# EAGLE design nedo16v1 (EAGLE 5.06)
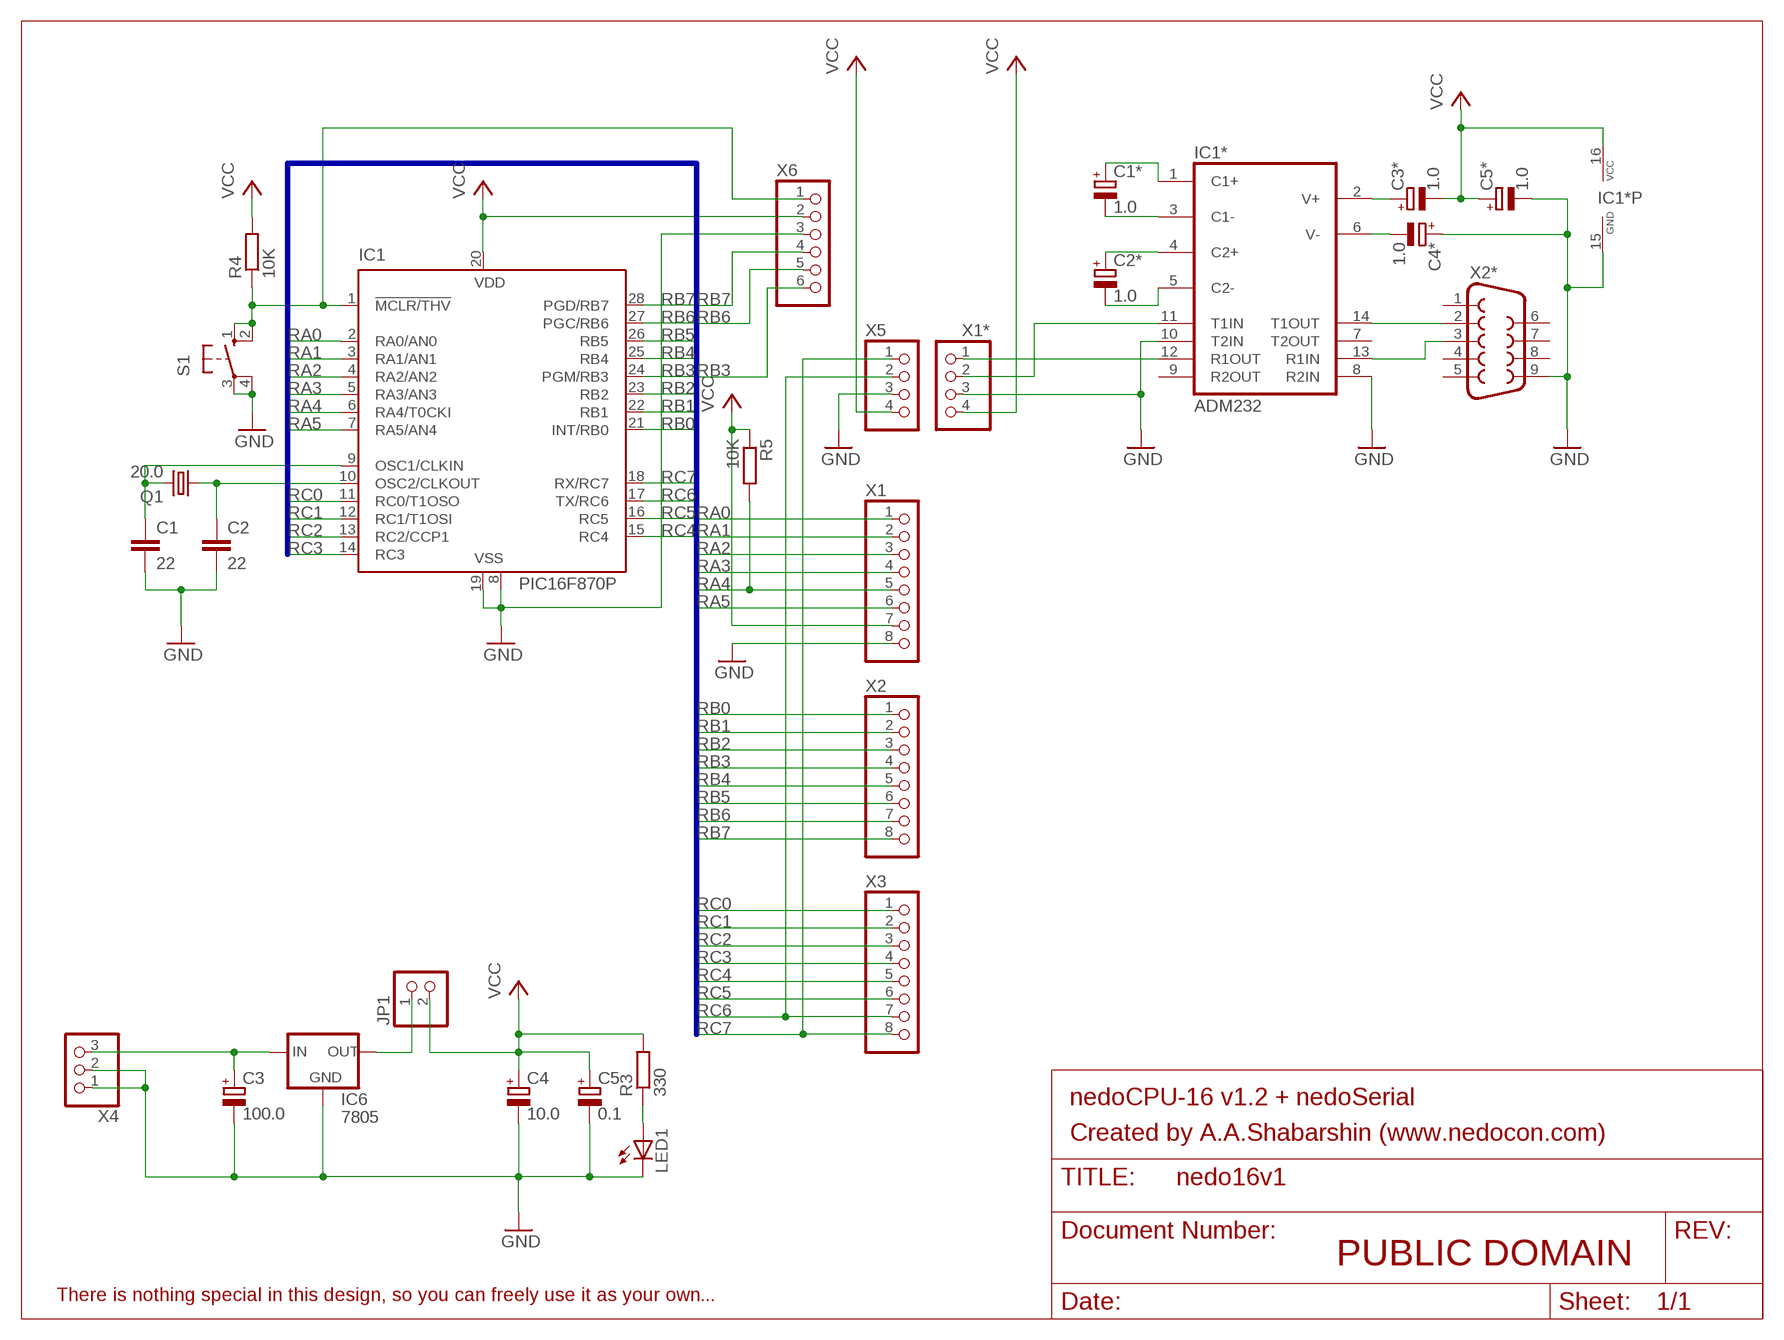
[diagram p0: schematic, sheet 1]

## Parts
C1  22  C-EU025-024X044  [C025-024X044]
C1*  1.0  CPOL-EUE2,5-6E  [E2,5-6E]
C2  22  C-EU025-024X044  [C025-024X044]
C2*  1.0  CPOL-EUE2,5-6E  [E2,5-6E]
C3  100.0  CPOL-EUE5-6  [E5-6]
C3*  1.0  CPOL-EUE2,5-6E  [E2,5-6E]
C4  10.0  CPOL-EUE2.5-6  [E2,5-6]
C4*  1.0  CPOL-EUE2,5-6E  [E2,5-6E]
C5  0.1  CPOL-EUE5-5  [E5-5]
C5*  1.0  CPOL-EUE2,5-6E  [E2,5-6E]
IC1  PIC16F870P  [DIL28-3]
IC1*  ADM232  MAX232  [DIL16]
IC6  7805  78XXS  [78XXS]
JP1  PINHD-1X2  [1X02]
LED1  LED5MM  [LED5MM]
Q1  20.0  CRYSTALHC49U-V  [HC49U-V]
R3  330  R-EU_0204/7  [0204/7]
R4  10K  R-EU_0204/7  [0204/7]
R5  10K  R-EU_0207/7  [0207/7]
S1  10-XX  [B3F-10XX]
X1  PINHD-1X8  [1X08]
X1*  PINHD-1X4  [1X04]
X2  PINHD-1X8  [1X08]
X2*  F09HP  [F09HP]
X3  PINHD-1X8  [1X08]
X4  PINHD-1X3  [1X03]
X5  PINHD-1X4  [1X04]
X6  PINHD-1X6  [1X06]

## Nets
GND: C1.2 C2.2 C3.- C4*.+ C4.- C5*.- C5.- IC1*.8(R2IN) IC1*.10(T2IN) IC1*.15(GND) IC1.8(VSS) IC1.19(VSS) IC6.GND LED1.K(C) S1.3(P) S1.4(P1) X1*.3 X1.8 X2*.9 X4.1 X4.2 X5.3 X6.3
N$1: IC1*.14(T1OUT) X2*.2
N$2: IC6.OUT JP1.1
N$3: IC1.1(!MCLR/THV) R4.1 S1.1(S) S1.2(S1) X6.1
N$7: LED1.A R3.1
N$10: C2.1 IC1.10(OSC2/CLKOUT) Q1.1
N$12: IC1*.13(R1IN) X2*.3
N$13: C4*.- IC1*.6(V-)
N$14: C3.+ IC6.IN X4.3
N$15: C3*.+ IC1*.2(V+)
N$16: C1.1 IC1.9(OSC1/CLKIN) Q1.2
N$17: C1*.- IC1*.3(C1-)
N$18: C2*.+ IC1*.4(C2+)
N$19: C2*.- IC1*.5(C2-)
N$20: C1*.+ IC1*.1(C1+)
RA0: IC1.2(RA0/AN0) X1.1
RA1: IC1.3(RA1/AN1) X1.2
RA2: IC1.4(RA2/AN2) X1.3
RA3: IC1.5(RA3/AN3) X1.4
RA4: IC1.6(RA4/T0CKI) R5.2 X1.5
RA5: IC1.7(RA5/AN4) X1.6
RB0: IC1.21(INT/RB0) X2.1
RB1: IC1.22(RB1) X2.2
RB2: IC1.23(RB2) X2.3
RB3: IC1.24(PGM/RB3) X2.4 X6.6
RB4: IC1.25(RB4) X2.5
RB5: IC1.26(RB5) X2.6
RB6: IC1.27(PGC/RB6) X2.7 X6.5
RB7: IC1.28(PGD/RB7) X2.8 X6.4
RC0: IC1.11(RC0/T1OSO) X3.1
RC1: IC1.12(RC1/T1OSI) X3.2
RC2: IC1.13(RC2/CCP1) X3.3
RC3: IC1.14(RC3) X3.4
RC4: IC1.15(RC4) X3.5
RC5: IC1.16(RC5) X3.6
RC6: IC1*.11(T1IN) IC1.17(TX/RC6) X1*.2 X3.7 X5.2
RC7: IC1*.12(R1OUT) IC1.18(RX/RC7) X1*.1 X3.8 X5.1
VCC: C3*.- C4.+ C5*.+ C5.+ IC1*.16(VCC) IC1.20(VDD) JP1.2 R3.2 R4.2 R5.1 X1*.4 X1.7 X5.4 X6.2
Unconnected: IC1*.7(T2OUT) IC1*.9(R2OUT) X2*.1 X2*.4 X2*.5 X2*.6 X2*.7 X2*.8

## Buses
RA[0..5],RB[0..7],RC[0..7]

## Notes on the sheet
- nedoCPU-16 v1.2 + nedoSerial
- Created by A.A.Shabarshin (www.nedocon.com)
- PUBLIC DOMAIN
- There is nothing special in this design, so you can freely use it as your own...

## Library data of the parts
C1 C2 = rcl:C-EU: CAPACITOR, European symbol
C1* C2* C3 C3* C4 C4* C5 C5* = rcl:CPOL-EU: POLARIZED CAPACITOR, European symbol
IC1 = microchip:PIC16*870: MICROCONTROLLER flash type
IC1* = maxim:MAX232: RS232 TRANSEIVER
IC6 = v-reg:78XXS: VOLTAGE REGULATOR
JP1 = pinhead:PINHD-1X2: PIN HEADER
LED1 = led:LED: LED
Q1 = crystal:CRYSTAL: CRYSTAL
R3-R5 = rcl:R-EU_: RESISTOR, European symbol
S1 = switch-omron:10-XX: OMRON SWITCH
X1-X3 = pinhead:PINHD-1X8: PIN HEADER
X1* X5 = pinhead:PINHD-1X4: PIN HEADER
X2* = con-subd:F09: SUB-D
X4 = pinhead:PINHD-1X3: PIN HEADER
X6 = pinhead:PINHD-1X6: PIN HEADER

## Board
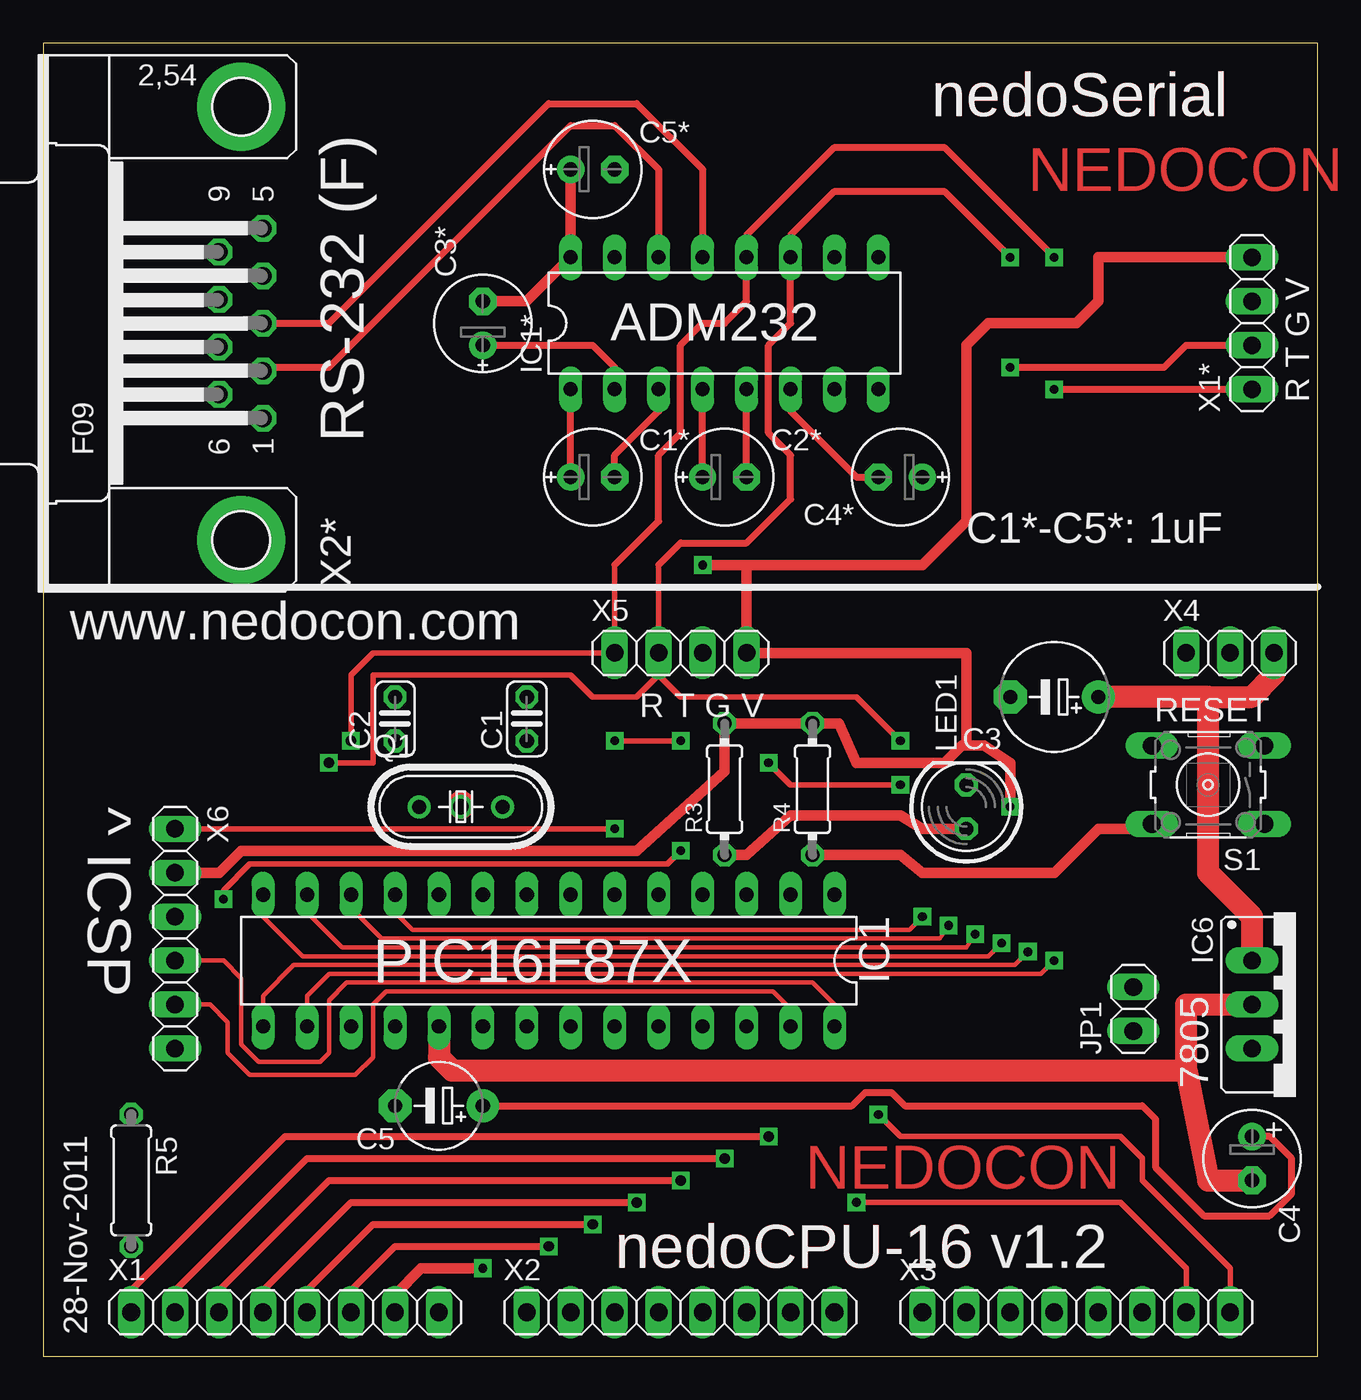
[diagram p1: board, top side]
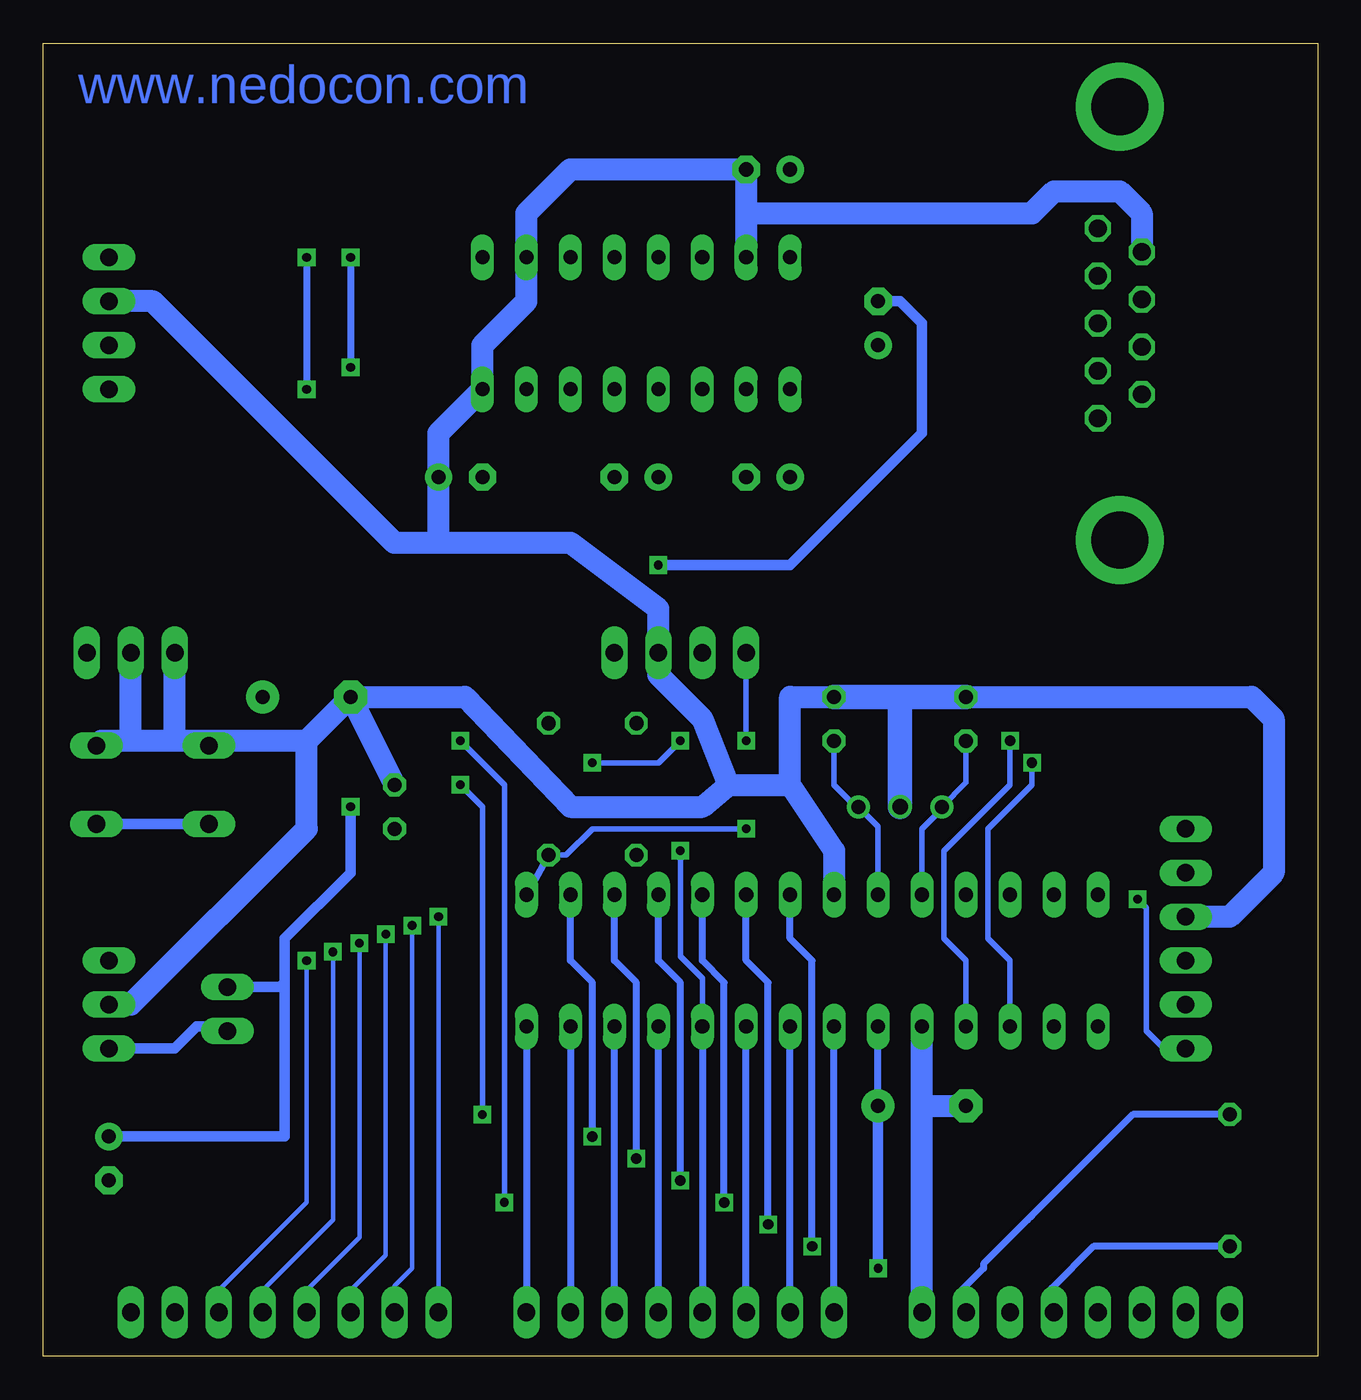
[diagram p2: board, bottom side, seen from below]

Size 73.64 x 75.87 mm. Coordinates in mm from the lower left corner, seen from the top.
Outline: 0,0 73.64,0 73.64,75.87 0,75.87 0,0
Copper layers (1*16): Top 0.035mm / dielectric 1.5mm / Bottom 0.035mm
Design rules "default *": minimum track width 10mil, minimum drill 16mil, track to track 10mil, track to pad 10mil, pad to pad 10mil, via to via 10mil, smd to smd 10mil, copper to edge 40mil, drill to drill 8mil, minimum pad ring 10mil, minimum via ring 8mil, stop-mask expansion 4mil, vias tented up to drill 0mil, thermal gap 10mil

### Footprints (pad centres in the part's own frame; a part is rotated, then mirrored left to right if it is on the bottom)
C025-024X044 = drill 0.813 octagon: 1 -1.27,0; 2 1.27,0
E2,5-6E = drill 0.813 pad 1.575 round: + -1.27,0 | drill 0.813 pad 1.575 octagon: - 1.27,0
E5-6 = drill 0.813 pad 1.905 round: + -2.54,0 | drill 0.813 pad 1.905 octagon: - 2.54,0
E2,5-6 = drill 0.813 pad 1.6 round: + -1.27,0 | drill 0.813 pad 1.6 octagon: - 1.27,0
E5-5 = drill 0.813 pad 1.905 round: + -2.54,0 | drill 0.813 pad 1.905 octagon: - 2.54,0
DIL28-3 = drill 0.813 long: 1 -16.51,-3.81; 2 -13.97,-3.81; 3 -11.43,-3.81; 4 -8.89,-3.81; 5 -6.35,-3.81; 6 -3.81,-3.81; 7 -1.27,-3.81; 8 1.27,-3.81; 9 3.81,-3.81; 10 6.35,-3.81; 11 8.89,-3.81; 12 11.43,-3.81; 13 13.97,-3.81; 14 16.51,-3.81; 15 16.51,3.81; 16 13.97,3.81; 17 11.43,3.81; 18 8.89,3.81; 19 6.35,3.81; 20 3.81,3.81; 21 1.27,3.81; 22 -1.27,3.81; 23 -3.81,3.81; 24 -6.35,3.81; 25 -8.89,3.81; 26 -11.43,3.81; 27 -13.97,3.81; 28 -16.51,3.81
DIL16 = drill 0.813 long: 1 -8.89,-3.81; 2 -6.35,-3.81; 3 -3.81,-3.81; 4 -1.27,-3.81; 5 1.27,-3.81; 6 3.81,-3.81; 7 6.35,-3.81; 8 8.89,-3.81; 9 8.89,3.81; 10 6.35,3.81; 11 3.81,3.81; 12 1.27,3.81; 13 -1.27,3.81; 14 -3.81,3.81; 15 -6.35,3.81; 16 -8.89,3.81
78XXS = drill 1.016 long: GND 0,-2.54; IN -2.54,-2.54; OUT 2.54,-2.54
1X02 = drill 1.016 long: 1 -1.27,0; 2 1.27,0
LED5MM = drill 0.813 octagon: A -1.27,0; K 1.27,0
HC49U-V = drill 0.813 round: 1 -2.413,0; 2 2.413,0
0204/7 = drill 0.813 octagon: 1 -3.81,0; 2 3.81,0
0207/7 = drill 0.813 octagon: 1 -3.81,0; 2 3.81,0
B3F-10XX = drill 1.016 long: 1 -3.251,2.261; 2 3.251,2.261; 3 -3.251,-2.261; 4 3.251,-2.261
1X08 = drill 1.016 long: 1 -8.89,0; 2 -6.35,0; 3 -3.81,0; 4 -1.27,0; 5 1.27,0; 6 3.81,0; 7 6.35,0; 8 8.89,0
1X04 = drill 1.016 long: 1 -3.81,0; 2 -1.27,0; 3 1.27,0; 4 3.81,0
F09HP = drill 1.016 octagon: 1 -5.486,-1.27; 2 -2.743,-1.27; 3 0,-1.27; 4 2.743,-1.27; 5 5.486,-1.27; 6 -4.115,1.27; 7 -1.372,1.27; 8 1.372,1.27; 9 4.115,1.27 | drill 3.302 pad 5.08 round: G1 -12.522,0; G2 12.522,0
1X03 = drill 1.016 long: 1 -2.54,0; 2 0,0; 3 2.54,0
1X06 = drill 1.016 long: 1 -6.35,0; 2 -3.81,0; 3 -1.27,0; 4 1.27,0; 5 3.81,0; 6 6.35,0

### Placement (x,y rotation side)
C1  27.94,36.83 90 top
C1*  31.75,50.8 0 top
C2  20.32,36.83 90 top
C2*  39.37,50.8 0 top
C3  58.42,38.1 180 top
C3*  25.4,59.69 90 top
C4  69.85,11.43 270 top
C4*  49.53,50.8 180 top
C5  22.86,14.48 180 top
C5*  31.75,68.58 0 top
IC1  29.21,22.86 180 top
IC1*  39.37,59.69 0 top
IC6  72.39,20.32 270 top
JP1  62.99,20.07 90 top
LED1  53.34,31.75 90 top
Q1  24.13,31.75 0 top
R3  39.37,32.77 90 top
R4  44.45,32.77 90 top
R5  5.08,10.16 270 top
S1  67.31,33.02 180 top
X1  13.97,2.54 0 top
X1*  69.85,59.69 90 top
X2  36.83,2.54 0 top
X2*  11.43,59.69 90 top
X3  59.69,2.54 0 top
X4  68.58,40.64 0 top
X5  36.83,40.64 0 top
X6  7.62,24.13 270 top

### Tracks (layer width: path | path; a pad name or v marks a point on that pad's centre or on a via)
GND  (via drill 0.9)
  Top 1.27: IC1.19 22.86,17.27 23.62,16.51 66.04,16.51 | 66.04,16.51 66.04,20.32 IC6.GND | 66.04,16.51 67.31,10.16 C4.-
  Top 1.422: v24.13,31.75 24.13,32
  Bottom 1.27: 22.86,14.48 IC1.19 | X1.8 22.86,14.48 | 22.86,14.48 C5.- | 58.42,35.56 63.78,35.56 | 63.78,35.56 S1.4 | 63.78,35.56 66.04,35.56 | 66.04,35.56 68.58,35.56 | 68.58,35.56 70.28,35.56 S1.3 | 68.58,35.56 X4.2 | 66.04,35.56 X4.1 | C3.- LED1.K | 58.42,35.56 58.42,30.48 68.58,20.32 IC6.GND | 58.42,35.56 C3.- | 34.04,33.02 35.56,31.75 43.18,31.75 49.28,38.1 C3.- | 34.04,33.02 30.48,33.02 | 34.04,33.02 35.56,36.83 38.1,39.37 X5.3 38.1,43.18 43.18,46.99 50.8,46.99 | 30.48,33.02 30.48,38.1 C1.2 | 30.48,33.02 27.94,29.21 IC1.8 | 50.8,46.99 53.34,46.99 67.31,60.96 X1*.3 | 33.02,66.55 C5*.- 43.18,68.58 45.72,66.04 IC1*.10 45.72,60.96 48.26,58.42 IC1*.8 50.8,53.34 C4*.+ 50.8,46.99 | 33.02,66.55 33.02,66.04 16.51,66.04 15.24,67.31 11.43,67.31 10.16,66.04 X2*.9 | 33.02,66.55 IC1*.15 | X6.3 5.08,25.4 2.54,27.94 2.54,36.83 3.81,38.1 C2.2
  Bottom 1.422: C1.2 24.13,38.1 | 24.13,38.1 v24.13,31.75 | 24.13,38.1 C2.2
N$1
  Top 0.406: IC1*.14 35.56,68.58 33.02,71.12 30.48,71.12 16.51,57.15 12.9,57.15 X2*.2
N$2
  Bottom 0.61: IC6.OUT 66.04,17.78 64.77,19.05 61.98,19.05 JP1.1
N$3  (via drill 0.5 pad 1.02)
  Top 0.305: X6.1 v33.02,30.48
  Top 0.61: R4.1 49.53,28.96 50.8,27.94 58.42,27.94 60.96,30.48 63.78,30.48 S1.2
  Bottom 0.305: R4.1 43.43,28.96 41.91,30.48 v33.02,30.48
  Bottom 0.406: R4.1 IC1.1
  Bottom 0.61: S1.2 S1.1
N$7
  Top 0.61: R3.1 40.64,28.96 43.18,31.24 49.53,31.24 50.8,30.48 LED1.A
N$10
  Bottom 0.305: C2.1 20.32,33.15 Q1.1 21.72,31.62 22.86,30.48 IC1.10
N$12
  Top 0.406: IC1*.13 38.1,68.58 34.29,72.39 29.21,72.39 16.51,59.69 X2*.3
N$13
  Top 0.406: C4*.- 46.99,50.8 43.18,54.61 IC1*.6
N$14
  Top 1.27: X4.3 71.12,39.37 69.85,38.1 67.31,38.1 | 67.31,38.1 C3.+ | 67.31,38.1 67.31,27.94 69.85,25.4 IC6.IN
N$15
  Top 0.406: IC1*.2 33.02,57.15 31.75,58.42 C3*.+
N$16
  Bottom 0.305: IC1.9 25.4,30.61 Q1.2 26.67,31.75 27.94,33.02 C1.1
N$17
  Top 0.406: C1*.- 33.02,52.07 35.56,54.61 IC1*.3
N$18
  Top 0.406: C2*.+ IC1*.4
N$19
  Top 0.406: C2*.- IC1*.5
N$20
  Top 0.406: C1*.+ IC1*.1
RA0  (via drill 0.6)
  Top 0.406: v41.91,12.7 13.97,12.7 5.08,3.81 X1.1
  Bottom 0.406: IC1.2 43.18,22.86 41.91,21.59 v41.91,12.7
RA1  (via drill 0.6)
  Top 0.406: v39.37,11.43 15.24,11.43 7.62,3.81 X1.2
  Bottom 0.406: IC1.3 40.64,22.86 39.37,21.59 v39.37,11.43
RA2  (via drill 0.6)
  Top 0.406: v36.83,10.16 16.51,10.16 10.16,3.81 X1.3
  Bottom 0.406: IC1.4 38.1,22.86 36.83,21.59 v36.83,10.16
RA3  (via drill 0.6)
  Top 0.406: v34.29,8.89 17.78,8.89 12.7,3.81 X1.4
  Bottom 0.406: IC1.5 35.56,22.86 34.29,21.59 v34.29,8.89
RA4  (via drill 0.6)
  Top 0.406: v31.75,7.62 19.05,7.62 15.24,3.81 X1.5
  Bottom 0.406: IC1.6 33.02,22.86 31.75,21.59 v31.75,7.62 | R5.2 12.95,6.35 15.37,3.94 15.37,2.67 X1.5
RA5  (via drill 0.6)
  Top 0.406: v29.21,6.35 20.32,6.35 17.78,3.81 X1.6
  Bottom 0.406: IC1.7 30.48,24.13 29.21,22.86 v29.21,6.35
RB0
  Bottom 0.406: X2.1 IC1.21
RB1
  Bottom 0.406: X2.2 IC1.22
RB2
  Bottom 0.406: X2.3 IC1.23
RB3  (via drill 0.5 pad 1.02)
  Top 0.305: v10.41,26.42 10.41,26.92 11.94,28.45 36.07,28.45 v36.83,29.21
  Bottom 0.305: X6.6 8.89,17.78 9.91,18.8 9.91,25.91 v10.41,26.42 | v36.83,29.21 36.83,23.11 35.56,21.84 IC1.24
  Bottom 0.406: IC1.24 X2.4
RB4
  Bottom 0.406: IC1.25 X2.5 38.1,1.27
RB5
  Bottom 0.406: X2.6 IC1.26
RB6
  Top 0.254: IC1.27 43.18,20.07 42.16,21.08 19.81,21.08 19.05,20.32 19.05,17.27 18.03,16.26 11.94,16.26 10.67,17.53 10.67,19.3 9.65,20.32 X6.5
  Bottom 0.406: IC1.27 X2.7
RB7
  Top 0.254: IC1.28 45.72,20.32 44.45,21.59 17.53,21.59 16.51,20.57 16.51,17.53 16,17.02 12.45,17.02 11.43,18.03 11.43,21.84 10.41,22.86 X6.4
  Bottom 0.406: IC1.28 X2.8
RC0  (via drill 0.5 pad 1.02)
  Top 0.254: IC1.11 20.32,25.65 21.34,24.64 50.04,24.64 v50.8,25.4
  Bottom 0.254: v50.8,25.4 X3.1
RC1  (via drill 0.5 pad 1.02)
  Top 0.254: IC1.12 17.78,25.91 19.56,24.13 51.82,24.13 v52.32,24.89
  Bottom 0.254: v52.32,24.89 52.32,5.08 53.34,4.06 X3.2
RC2  (via drill 0.5 pad 1.02)
  Top 0.254: IC1.13 15.24,25.65 17.27,23.62 53.34,23.62 v53.85,24.38
  Bottom 0.254: v53.85,24.38 53.85,5.84 55.88,3.81 X3.3
RC3  (via drill 0.5 pad 1.02)
  Top 0.254: IC1.14 12.7,25.4 14.99,23.11 54.61,23.11 v55.37,23.88
  Bottom 0.254: v55.37,23.88 55.37,6.86 58.42,3.81 X3.4
RC4  (via drill 0.5 pad 1.02)
  Top 0.254: IC1.15 12.7,20.83 14.48,22.61 56.13,22.61 v56.9,23.37
  Bottom 0.254: v56.9,23.37 56.9,7.87 60.96,3.81 X3.5
RC5  (via drill 0.5 pad 1.02)
  Top 0.254: IC1.16 15.24,20.83 16.51,22.1 57.66,22.1 v58.42,22.86
  Bottom 0.254: v58.42,22.86 58.42,8.89 63.5,3.81 X3.6
RC6  (via drill 0.5 pad 1.02, 0.6)
  Top 0.305: 35.56,45.72 X5.2 35.56,39.37 | v16.51,34.29 19.05,34.29 19.05,39.37 30.48,39.37 31.75,38.1 34.29,38.1 35.56,39.37 | X3.7 66.04,5.08 62.23,8.89 v46.99,8.89 | v49.53,35.56 46.99,38.1 36.83,38.1 35.56,39.37
  Top 0.406: 35.56,45.72 36.83,46.99 40.64,46.99 43.18,49.53 43.18,52.07 41.91,53.34 41.91,58.42 43.18,59.69 IC1*.11 43.18,64.77 45.72,67.31 52.07,67.31 v55.88,63.5 | v55.88,57.15 64.77,57.15 66.04,58.42 X1*.2 71.12,58.42
  Bottom 0.305: IC1.17 17.78,22.86 19.05,24.13 19.05,30.48 16.51,33.02 v16.51,34.29 | v46.99,8.89 46.99,33.02 v49.53,35.56
  Bottom 0.406: v55.88,63.5 v55.88,57.15
RC7  (via drill 0.5 pad 1.02, 0.6)
  Top 0.305: 33.02,45.72 X5.1 19.05,40.64 17.78,39.37 v17.78,35.56 | X3.8 68.58,5.08 63.5,10.16 63.5,11.43 62.23,12.7 49.53,12.7 v48.26,13.97 | v49.53,33.02 43.18,33.02 v41.91,34.29 | v33.02,35.56 v36.83,35.56
  Top 0.406: 33.02,45.72 35.56,48.26 35.56,52.07 36.83,53.34 36.83,58.42 38.1,59.69 39.37,59.69 40.64,60.96 IC1*.12 40.64,64.77 45.72,69.85 52.07,69.85 v58.42,63.5 | v58.42,55.88 X1*.1
  Bottom 0.305: IC1.18 20.32,22.86 21.59,24.13 21.59,29.21 17.78,33.02 v17.78,35.56 | v48.26,13.97 48.26,31.75 v49.53,33.02 | v41.91,34.29 38.1,34.29 v36.83,35.56 | X5.1 v33.02,35.56
  Bottom 0.406: v58.42,63.5 v58.42,55.88
VCC  (via drill 0.5 pad 1.02)
  Top 0.406: C5.+ 46.74,14.48 47.5,15.24 49.02,15.24 49.78,14.48 63.5,14.48 64.26,13.72 64.26,10.92 67.06,8.13 70.87,8.13 72.14,9.4 72.14,11.43 70.87,12.7 C4.+
  Top 0.61: v25.4,5.08 21.84,5.08 20.32,3.56 X1.7 | 53.34,35.31 53.09,35.31 52.07,34.29 46.99,34.29 45.97,36.58 R4.2 R3.2 39.37,33.78 34.29,29.21 11.43,29.21 10.16,27.94 X6.2 | 53.34,35.31 54.36,35.31 55.88,34.29 v55.88,31.75 | X1*.4 60.96,63.5 60.96,60.96 59.69,59.69 54.61,59.69 53.34,58.42 53.34,48.26 50.8,45.72 40.64,45.72 | C3*.- 27.94,60.96 IC1*.16 C5*.+ | 40.64,45.72 v38.1,45.72 | 40.64,45.72 X5.4 53.34,40.64 53.34,35.31
  Bottom 0.406: C5.+ IC1.20 | R5.1 10.67,13.97 16.76,7.87 | 16.76,7.87 16.51,8.13 | 16.76,7.87 19.3,5.33 19.3,5.08 20.57,3.81 20.57,2.79 X1.7
  Bottom 0.61: v25.4,5.08 C5.+ | v38.1,45.72 30.48,45.72 22.86,53.34 22.86,59.69 24.13,60.96 C3*.- | JP1.2 59.94,21.34 59.69,21.59 | 59.69,21.59 59.69,12.7 C4.+ | v55.88,31.75 55.88,27.94 59.69,24.13 59.69,21.59

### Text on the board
Top: nedoSerial | NEDOCON | NEDOCON | nedoCPU-16
Bottom: www.nedocon.com
tNames: nedoSerial | ADM232 | R T G V | RS-232 (F) | C1*-C5*: 1uF | www.nedocon.com | R T G V | RESET | ^ ICSP | PIC16F87X | 7805 | nedoCPU-16 v1.2 | 28-Nov-2011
